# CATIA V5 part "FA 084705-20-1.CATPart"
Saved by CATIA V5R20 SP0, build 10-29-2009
Part number: FA 084705-20-1
Revision: ANY
Definition: UNKNOWN
Nomenclature: FA 084705-20-1
Source: Unknown
Bounding box of the stored display mesh (mm): x -3.98 to 3.804, y -10 to 10, z -4 to 4
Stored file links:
  C:\Users\Utente\Desktop\IO LAVORO\3D X SITO CF\CUMSA\3D files FA\FA 084705-20\FA 084705-20-1.CATPart

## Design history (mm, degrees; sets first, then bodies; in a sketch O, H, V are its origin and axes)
Body1 "Cortar-Extruir6" (main body)
  Solid1: solid without history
